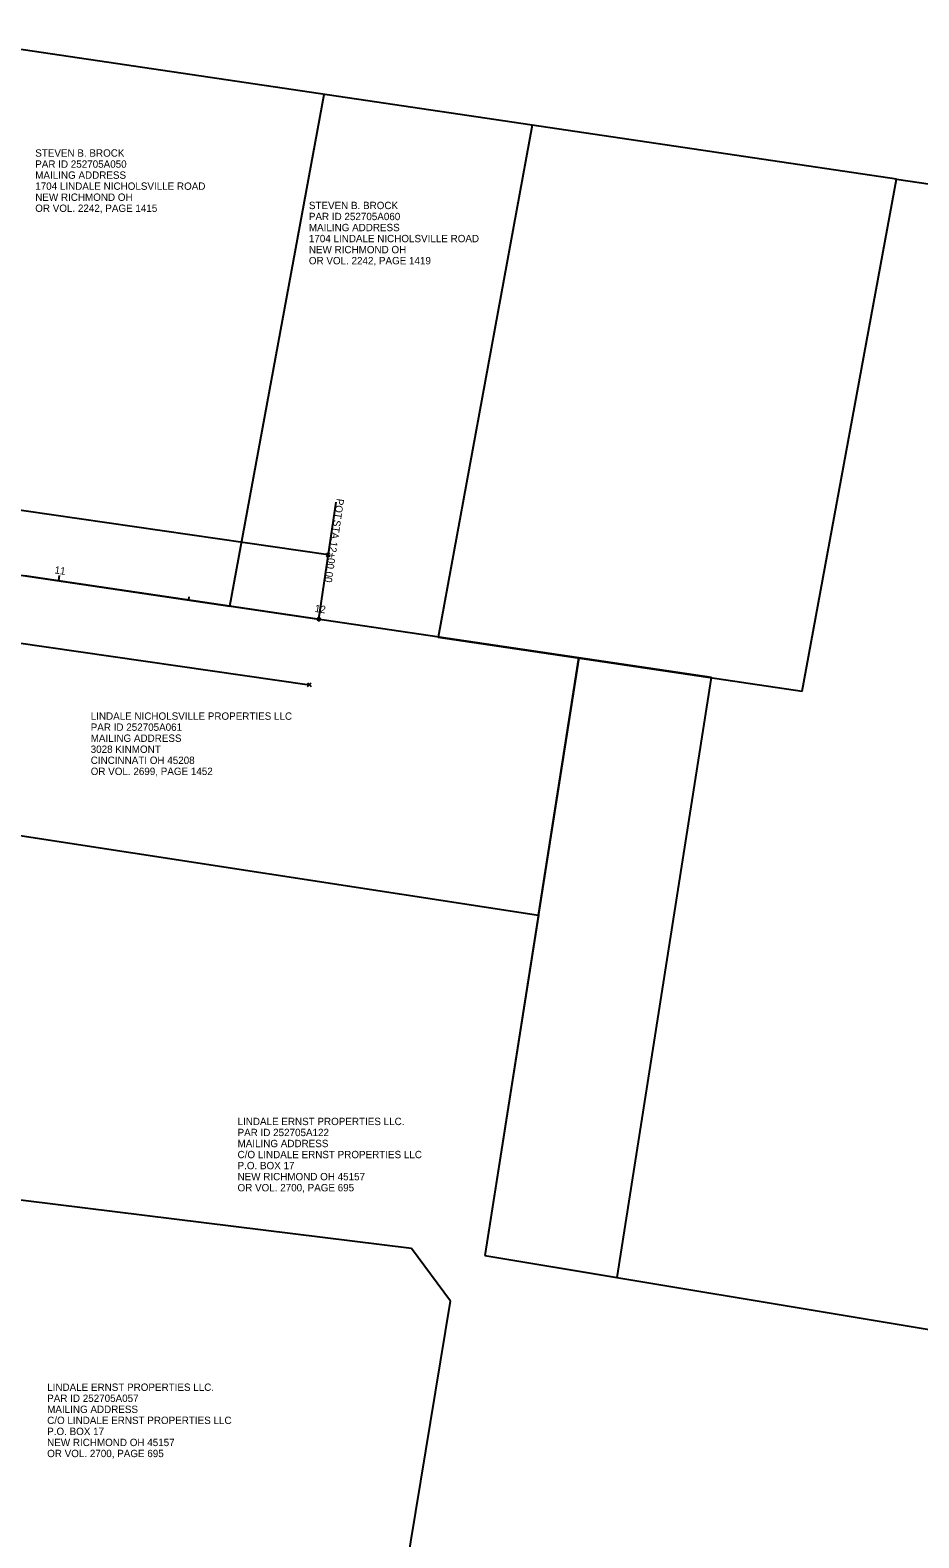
# Model space of a CAD drawing. Extents: x 1479990 to 1483389, y 364592 to 367421.
# Drawn here: x 1482360 to 1482698, y 365101 to 365675 of the extents above; entities that cross this region are included whole.
import ezdxf

# ---------------------------------------------------------------- set-up
doc = ezdxf.new("R2010")
doc.units = 0
for name, color, linetype in [('DR_X_Ditch', 7, 'Continuous'), ('DT_X_Contour_Minor', 7, 'Continuous'), ('DT_X_Terrain_Ground_Line', 7, 'Continuous'), ('DV_X_Lot_Line', 7, 'Continuous'), ('DV_X_Property_Line', 7, 'Continuous'), ('PV_X_Curb', 7, 'Continuous'), ('PV_X_Shoulder', 7, 'Continuous'), ('SV_X_Control_Cells_Found', 7, 'Continuous')]:
    doc.layers.add(name, color=color, linetype=linetype)

msp = doc.modelspace()

# ---------------------------------------------------------------- linework, layer by layer
at = {"layer": 'DT_X_Contour_Minor'}
for p, q in [((1482551.27, 365638.85), (1482307.05, 365675.02)), ((1482436.32, 365455.85), (1482472.14, 365650.57)), ((1482505.3, 365211.5), (1482259.97, 365241.93)), ((1482520.23, 365191.53), (1482505.3, 365211.5)), ((1482495.49, 365041.57), (1482520.23, 365191.53))]:
    msp.add_line(p, q, dxfattribs=at)
at = {"layer": 'DT_X_Terrain_Ground_Line'}
for p, q in [((1482371.19, 365465.61), (1482371.48, 365467.59)), ((1482420.65, 365458.29), (1482420.82, 365459.48)), ((1482470.11, 365450.97), (1482470.4, 365452.95))]:
    msp.add_line(p, q, dxfattribs=at)
at = {"layer": 'DV_X_Lot_Line'}
for p, q in [((1482551.27, 365638.85), (1482515.45, 365444.13)), ((1482689.75, 365618.34), (1482551.27, 365638.85)), ((1482653.93, 365423.62), (1482689.75, 365618.34)), ((1482689.75, 365618.34), (1483032.99, 365567.5)), ((1482274.15, 365479.87), (1482436.32, 365455.85)), ((1482568.96, 365436.21), (1482358.23, 365467.42)), ((1482515.45, 365444.13), (1482653.93, 365423.62)), ((1482568.96, 365436.21), (1482533.29, 365208.95)), ((1482553.6, 365338.35), (1482568.96, 365436.21)), ((1482619.4, 365428.74), (1482568.96, 365436.21)), ((1482583.58, 365200.54), (1482619.4, 365428.74)), ((1482342.33, 365370.88), (1482553.6, 365338.35)), ((1482553.6, 365338.35), (1482533.29, 365208.95)), ((1482533.29, 365208.95), (1482583.58, 365200.54)), ((1482533.29, 365208.95), (1483328.2, 365076.11))]:
    msp.add_line(p, q, dxfattribs=at)
at = {"layer": 'DV_X_Property_Line'}
for p, q in [((1482301.17, 365500.42), (1482473.65, 365475.51)), ((1482354.09, 365442.26), (1482466.51, 365426.02))]:
    msp.add_line(p, q, dxfattribs=at)
at = {"layer": 'PV_X_Curb'}
msp.add_line((1482272.26, 365480.24), (1482470.11, 365450.97), dxfattribs=at)
at = {"layer": 'PV_X_Shoulder'}
msp.add_line((1482470.11, 365450.97), (1482476.7, 365495.48), dxfattribs=at)
msp.add_circle((1482470.11, 365450.97), 0.6, dxfattribs=at)
at = {"layer": 'SV_X_Control_Cells_Found'}
for p, q in [((1482472.99, 365474.84), (1482474.32, 365476.18)), ((1482472.99, 365476.18), (1482474.32, 365474.84)), ((1482465.84, 365425.35), (1482467.17, 365426.69)), ((1482465.84, 365426.69), (1482467.17, 365425.35))]:
    msp.add_line(p, q, dxfattribs=at)

# ---------------------------------------------------------------- texts
at = {"layer": 'DR_X_Ditch'}
for s, p in [('STEVEN B. BROCK', (1482362.26, 365626.88)), ('PAR ID 252705A050', (1482362.26, 365622.68)), ('MAILING ADDRESS', (1482362.26, 365618.48)), ('1704 LINDALE NICHOLSVILLE ROAD', (1482362.26, 365614.28)), ('OR VOL. 2242, PAGE 1415', (1482362.26, 365605.88)), ('NEW RICHMOND OH', (1482362.26, 365610.08)), ('STEVEN B. BROCK', (1482466.32, 365606.94)), ('PAR ID 252705A060', (1482466.32, 365602.74)), ('1704 LINDALE NICHOLSVILLE ROAD', (1482466.32, 365594.34)), ('MAILING ADDRESS', (1482466.32, 365598.54)), ('NEW RICHMOND OH', (1482466.32, 365590.14)), ('OR VOL. 2242, PAGE 1419', (1482466.32, 365585.94)), ('LINDALE NICHOLSVILLE PROPERTIES LLC', (1482383.35, 365412.68)), ('PAR ID 252705A061', (1482383.35, 365408.48)), ('3028 KINMONT', (1482383.35, 365400.08)), ('MAILING ADDRESS', (1482383.35, 365404.28)), ('CINCINNATI OH 45208', (1482383.35, 365395.88)), ('OR VOL. 2699, PAGE 1452', (1482383.35, 365391.68)), ('LINDALE ERNST PROPERTIES LLC.', (1482439.2, 365258.5)), ('PAR ID 252705A122', (1482439.2, 365254.3)), ('MAILING ADDRESS', (1482439.2, 365250.1)), ('C/O LINDALE ERNST PROPERTIES LLC', (1482439.2, 365245.9)), ('P.O. BOX 17', (1482439.2, 365241.7)), ('OR VOL. 2700, PAGE 695', (1482439.2, 365233.3)), ('NEW RICHMOND OH 45157', (1482439.2, 365237.5)), ('LINDALE ERNST PROPERTIES LLC.', (1482366.8, 365157.39)), ('PAR ID 252705A057', (1482366.8, 365153.19)), ('MAILING ADDRESS', (1482366.8, 365148.99)), ('C/O LINDALE ERNST PROPERTIES LLC', (1482366.8, 365144.79)), ('P.O. BOX 17', (1482366.8, 365140.59)), ('NEW RICHMOND OH 45157', (1482366.8, 365136.39)), ('OR VOL. 2700, PAGE 695', (1482366.8, 365132.19))]:
    msp.add_text(s, height=2.8, dxfattribs=at).set_placement(p)
at = {"layer": 'DT_X_Terrain_Ground_Line'}
for s, p in [('11', (1482369.47, 365468.39)), ('12', (1482468.4, 365453.75))]:
    msp.add_text(s, height=2.8, rotation=351.58308, dxfattribs=at).set_placement(p)
at = {"layer": 'PV_X_Shoulder'}
for s, p in [('POT', (1482476.95, 365496.95)), (' STA. ', (1482475.91, 365489.89)), ('12+00.00', (1482474.54, 365480.67))]:
    msp.add_text(s, height=2.8, rotation=261.58308, dxfattribs=at).set_placement(p)

doc.saveas('drawing.dxf')
